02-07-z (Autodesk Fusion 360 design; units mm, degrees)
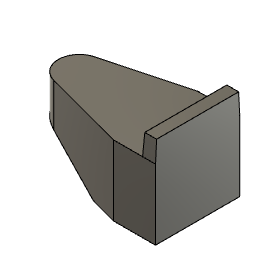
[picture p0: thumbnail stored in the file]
sketch "スケッチ1" plane through (0, 0, 0) normal (0, 0, 1) x axis (1, 0, 0)
  line L1 (-50, 25) -> (50, 25)
  line L2 (-50, -25) -> (-50, 25)
  line L3 (50, -25) -> (-50, -25)
  line L4 (50, 25) -> (50, -25)
  line L5 (-50, -25) -> (50, 25)
  line L6 (50, -25) -> (-50, 25)
  point P6 (0, 0)
  point P1 (0, 0)
  point P2 (50, 25)
  point P3 (-50, 25)
  point P5 (50, -25)
  horizontal L1
  perpendicular L1 L2
  parallel L1 L3
  parallel L2 L4
  coincident L5 P6
  coincident L6 P6
  coincident P1 P6
  dimension "d1" distance P2 P3 = 100
  dimension "d2" distance P2 P5 = 50
extrude "押し出し1" new body sketch "スケッチ1" profile of L1 L2 L3 L4 distance 60
sketch "スケッチ2" plane through (0, 25, 0) normal (0, 1, 0) x axis (-1, 0, 0)
  line L1 (50, 30) -> (50, -30)
  line L2 (-50, 30) -> (50, 30)
  line L3 (-50, -30) -> (-50, 30)
  line L4 (50, -30) -> (-50, -30)
  line L5 (-50, -30) -> (-40, -30)
  line L6 (-50, 30) -> (-50, -30)
  line L7 (-40, 30) -> (-50, 30)
  line L8 (-40, -30) -> (-40, 30)
  point P5 (-50, -30)
  point P7 (-50, -30)
  point P4 (-50, 30)
  point P8 (-50, 30)
  point P6 (-40, -30)
  horizontal L5
  vertical L6
  horizontal L7
  vertical L8
  coincident P5 P7
  coincident P4 P8
  dimension "d5" distance P6 P7 = 10
extrude "押し出し2" add sketch "スケッチ2" profile of L2 L3 L4 L5 L6 L7 L8 along normal blind 15 taper -3
sketch "スケッチ4" plane through (0, 0, 30) normal (0, 0, 1) x axis (1, 0, 0)
  line L1 (50, 25) -> (50, -25)
  line L2 (-50, 25) -> (40, 25)
  line L3 (-50, -25) -> (-50, 25)
  line L4 (50, -25) -> (-50, -25)
  line L5 (0, -25) -> (-50, -25)
  line L6 (-50, 0) -> (0, -25)
  line L7 (-50, -25) -> (-50, 0)
  line L8 (40, 25) -> (50, 25)
  point P7 (-50, -25)
  point P9 (-50, 0)
  point P8 (0, -25)
  parallel L3 L7
  collinear L3 L7
  collinear L4 L5
  dimension "d10" distance P7 P9 = 25
  dimension "d11" distance P7 P8 = 50
extrude "押し出し3" cut sketch "スケッチ4" profile of L3 L4 L5 L6 L7 no distance stored
sketch "スケッチ5" plane through (0, 25, 0) normal (0, 1, 0) x axis (-1, 0, 0)
  line L1 (-40, -30) -> (-40, 30)
  line L2 (50, -30) -> (-40, -30)
  line L3 (50, 30) -> (50, -30)
  line L4 (-40, 30) -> (50, 30)
  line L5 (-19.2139, -30) -> (38.8693, -14.4924)
  line L6 (-49.2139, -30) -> (-19.2139, -30)
  line L7 (-49.2139, 30) -> (-49.2139, -30)
  line L8 (-19.2139, 30) -> (-49.2139, 30)
  line L9 (38.8693, 14.4924) -> (-19.2139, 30)
  line L10 (-49.2139, -29.2139) -> (-49.2139, 29.2139)
  arc A1 centre (35, 0) radius 15 clockwise from (38.8693, 14.4924) to (38.8693, -14.4924)
  point P7 (-19.2139, -30)
  point P8 (-49.2139, -30)
  horizontal L6
  perpendicular L6 L7
  perpendicular L7 L8
  tangent L5 A1
  tangent L9 A1
  equal L5 L9
  equal L6 L8
  collinear L2 L6
  collinear L4 L8
  collinear L7 L10
  tangent L3 A1
  dimension "d13" distance P7 P8 = 30
  dimension "d14" radius A1 = 15
extrude "押し出し4" sketch "スケッチ5" profile of L1 L2 L4 L5 L6 L7 L8 L9 A1 L10 no distance stored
